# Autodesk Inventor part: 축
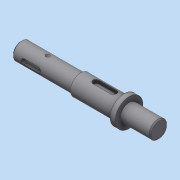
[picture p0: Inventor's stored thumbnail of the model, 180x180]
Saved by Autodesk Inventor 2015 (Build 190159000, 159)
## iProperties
Created: 2023-05
Part Number: 축
Material: 일반
Document SubType Name: Modeling
Designer: Administrator
Density: 1 g/cm^3
Appearance: 기본값
Author: Administrator
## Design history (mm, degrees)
sketch "스케치1"
  geometry: L1 (0, 0)-(134, 0); L2 (134, 0)-(134, 8.5); L3 (134, 8.5)-(76, 8.5); L4 (76, 8.5)-(76, 10); L5 (76, 10)-(34, 10); L6 (34, 10)-(34, 13.5); L7 (34, 13.5)-(29, 13.5); L8 (29, 13.5)-(29, 8.5); L9 (29, 8.5)-(0, 8.5); L10 (0, 8.5)-(0, 0)
  constraints: 20 end point, 7 perpendicular, 2 horizontal, 1 vertical
  dimensions: "d0" = 134 distance of L1.start L1.end; "d1" = 17 diameter of L3 L1; "d2" = 20 diameter of L5 L1; "d3" = 17 diameter of L9 L1; "d4" = 27 diameter of L7 L1; "d5" = 5 distance of L6.end L7.end; "d6" = 58 distance of L2.end L3.end; "d7" = 42 distance of L4.end L5.end
revolve "회전1" sketch "스케치1" stored, may be unused: angle "d8" = 90 deg
node "작업 평면1"
sketch "스케치2"
  geometry: L1 (26, 9.069)-(26, -9.069) reference; L2 (26, -9.069)-(21, -9.069) reference; L3 (21, -9.069)-(21, 0) reference; L4 (21, 0)-(21, 9.069) reference; L5 (21, 9.069)-(26, 9.069) reference; L6 (21, 0)-(-21, 0) reference; L7 (26, 9.069)-(26, -9.069) reference; L8 (26, -9.069)-(21, -9.069) reference; L9 (21, -9.069)-(21, 0) reference; L10 (21, 0)-(21, 9.069) reference; L11 (21, 9.069)-(26, 9.069) reference; L12 (21, 0)-(-21, 0) reference; L13 (-9, 0)-(14, 0); L14 (-6, -3)-(11, -3); L15 (11, 3)-(-6, 3); A1 r 3 centre (-6, 0) between (-6, 3) and (-6, -3); A2 r 3 centre (11, 0) between (11, -3) and (11, 3); 2 further points
  constraints: 8 end point, 6 point on circle, 4 point on line, 4 tangent, 2 centre point, 1 midpoint, 1 parallel
  dimensions: "d9" = 7 distance from line of L4 L13.end; "d10" = 23 distance of L13.start L13.end; "d11" = 6 distance between parallel lines of L14 L15
extrude "돌출1" cut sketch "스케치2" distance "d12" = 3.5; taper "d13" = 0 deg
node "작업 평면2"
sketch "스케치3"
  geometry: L1 (-105, 0)-(-76, 0) reference; L2 (-76, -10.488)-(-76, 0) reference; L3 (-71, -10.488)-(-76, -10.488) reference; L4 (-71, -5.268)-(-71, -10.488) reference; L5 (-29, -5.268)-(-71, -5.268) reference; L6 (-29, 0)-(-29, -5.268) reference; L7 (-29, 0)-(29, 0) reference; L8 (-76, 0)-(-76, 10.488) reference; L9 (-76, 10.488)-(-71, 10.488) reference; L10 (-71, 10.488)-(-71, 5.268) reference; L11 (-71, 5.268)-(-29, 5.268) reference; L12 (-29, 5.268)-(-29, 0) reference; L13 (20.5, 0)-(1.5, 0); L14 (18, -2.5)-(4, -2.5); L15 (4, 2.5)-(18, 2.5); L16 (29, -8.5)-(29, 8.5) reference; A1 r 2.5 centre (18, 0) between (18, -2.5) and (18, 2.5); A2 r 2.5 centre (4, 0) between (4, 2.5) and (4, -2.5); 1 further point
  constraints: 8 end point, 6 point on circle, 4 point on line, 4 tangent, 2 centre point, 1 midpoint, 1 parallel
  dimensions: "d14" = 8.5 distance from line of L16 L13.start; "d15" = 19 distance of L13.end L13.start; "d16" = 5 distance between parallel lines of L14 L15
extrude "돌출2" cut sketch "스케치3" distance "d17" = 3; taper "d18" = 0 deg
sketch "스케치5"
  geometry: L1 (76, 8.5)-(134, 8.5) reference; L2 (108, 8.5)-(108, 6.5); L3 (108, 6.5)-(110, 8.5); L4 (76, -10)-(76, 10) reference; 1 further point
  constraints: 4 end point, 2 point on line, 1 vertical
  dimensions: "d27" = 32 distance between parallel lines of L2 L4; "d28" = 45 deg angle of L3 L2; "d29" = 2 distance of L2.start L3.end
revolve "회전2" sketch "스케치5" stored, may be unused: angle "d30" = 90 deg
chamfer "모따기1" distance "d31" = 1; stored, may be unused: second distance "d32" = 2, angle "d33" = 45 deg
node "솔리드1"
node "절단 모서리 투영1"
node "절단 모서리 투영2"
node "절단 모서리 투영3"
